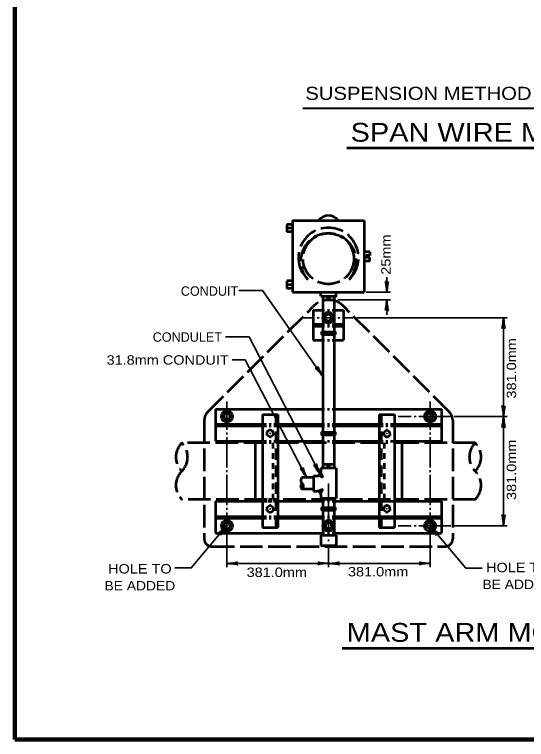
# Model space of a CAD drawing. Extents: x -35 to 821, y -10 to 534.
# Drawn here: x 22.7 to 185.9, y 1.2 to 232.3 of the extents above; entities that cross this region are included whole.
import ezdxf
from ezdxf.enums import TextEntityAlignment as Align

# ---------------------------------------------------------------- set-up
doc = ezdxf.new("R2010")
doc.units = 0
doc.header["$LTSCALE"] = 1.2
for name, pattern in [('LONG_DASHED', [7.5, 6, -1.5]), ('MEDIUM_DASHED', [4.5, 3, -1.5]), ('SHORT_DASHED', [2.7, 1.5, -1.2])]:
    doc.linetypes.add(name, pattern=pattern)
doc.layers.add('1', color=7, linetype='Continuous', lineweight=35)

msp = doc.modelspace()

# ---------------------------------------------------------------- hatches: boundary and pattern name
at = {"layer": '1'}
for points in [[(90.519, 104.186, 1), (90.219, 104.186, 1)], [(155.33, 104.153, 1), (155.03, 104.153, 1)], [(104.352, 98.795, 1), (104.052, 98.795, 1)], [(141.55, 98.74, 1), (141.25, 98.74, 1)], [(104.348, 74.708, 1), (104.047, 74.708, 1)], [(141.55, 74.781, 1), (141.25, 74.781, 1)], [(90.548, 69.401, 1), (90.248, 69.401, 1)], [(122.966, 69.335, 1), (122.666, 69.335, 1)], [(155.345, 69.345, 1), (155.045, 69.345, 1)]]:
    msp.add_hatch(color=256, dxfattribs=at).paths.add_polyline_path(points)

# ---------------------------------------------------------------- linework, layer by layer
at = {"layer": '1', "lineweight": 40}
msp.add_line((114.635, 202.436), (284.928, 202.436), dxfattribs=at)
at = {"layer": '1', "lineweight": 53}
for p, q in [((128.665, 189.734), (273.471, 189.734)), ((111.353, 166.568), (111.353, 143.768)), ((111.353, 166.568), (134.194, 166.568)), ((134.194, 166.568), (134.194, 143.768)), ((111.353, 165.368), (109.553, 165.368)), ((109.553, 165.368), (109.553, 162.968)), ((111.353, 164.168), (109.553, 164.168)), ((111.353, 162.968), (109.553, 162.968)), ((135.994, 156.668), (134.194, 156.668)), ((135.994, 155.468), (134.794, 155.468)), ((135.994, 156.668), (135.994, 155.468)), ((135.994, 153.668), (135.994, 154.868)), ((135.994, 153.668), (134.194, 153.668)), ((111.353, 147.368), (109.553, 147.368)), ((109.553, 147.368), (109.553, 144.968)), ((111.353, 146.168), (109.553, 146.168)), ((111.353, 144.968), (109.553, 144.968)), ((111.353, 143.768), (134.194, 143.768)), ((120.353, 142.55), (120.353, 143.75)), ((120.994, 142.55), (120.994, 131.15)), ((120.994, 141.35), (124.594, 141.35)), ((122.194, 141.95), (123.394, 141.95)), ((124.594, 142.55), (124.594, 138.049)), ((122.453, 138.05), (123.094, 138.05)), ((124.594, 138.035), (124.594, 131.15)), ((127.594, 138.05), (127.594, 128.45)), ((121.862, 135.102), (121.862, 136.262)), ((123.687, 135.682), (123.687, 136.262)), ((123.687, 135.682), (123.687, 135.102)), ((117.953, 132.95), (120.994, 132.95)), ((120.994, 132.95), (121.553, 132.95)), ((122.453, 133.55), (123.094, 133.55)), ((122.453, 132.95), (123.094, 132.95)), ((123.994, 133.55), (124.594, 133.55)), ((123.994, 132.95), (124.594, 132.95)), ((124.594, 133.55), (127.594, 133.55)), ((124.594, 132.95), (127.594, 132.95)), ((120.994, 131.15), (124.594, 131.15)), ((120.994, 130.25), (124.594, 130.25)), ((120.994, 130.25), (120.994, 101.15)), ((124.594, 130.25), (124.594, 99.2)), ((117.953, 128.45), (121.553, 128.45)), ((122.453, 128.45), (123.094, 128.45)), ((123.994, 128.45), (127.594, 128.45)), ((86.794, 106.55), (121.553, 106.55)), ((122.453, 106.55), (123.094, 106.55)), ((123.994, 106.55), (158.794, 106.55)), ((158.794, 106.55), (158.794, 96.35)), ((89.482, 103.616), (89.482, 104.777)), ((91.307, 104.197), (91.307, 104.777)), ((91.307, 104.197), (91.307, 103.616)), ((101.794, 104.75), (101.794, 68.75)), ((101.794, 104.75), (106.594, 104.75)), ((106.594, 104.75), (106.594, 68.75)), ((138.994, 104.75), (138.994, 68.75)), ((138.994, 104.75), (143.794, 104.75)), ((143.794, 104.75), (143.794, 68.75)), ((154.282, 103.616), (154.282, 104.777)), ((156.107, 104.197), (156.107, 104.777)), ((156.107, 104.197), (156.107, 103.616)), ((86.794, 101.75), (102.994, 101.75)), ((103.894, 101.75), (104.494, 101.75)), ((105.394, 101.75), (121.553, 101.75)), ((122.453, 101.75), (123.094, 101.75)), ((123.994, 101.75), (140.194, 101.75)), ((141.094, 101.75), (141.694, 101.75)), ((142.594, 101.75), (158.794, 101.75)), ((86.794, 101.15), (102.994, 101.15)), ((103.293, 98.196), (103.293, 99.356)), ((103.894, 101.15), (104.494, 101.15)), ((105.118, 98.776), (105.118, 99.356)), ((105.394, 101.15), (121.553, 101.15)), ((120.994, 101.15), (120.994, 99.2)), ((122.453, 101.15), (123.094, 101.15)), ((123.994, 101.15), (140.194, 101.15)), ((141.094, 101.15), (141.694, 101.15)), ((142.594, 101.15), (158.794, 101.15)), ((105.118, 98.776), (105.118, 98.196)), ((120.994, 99.2), (124.594, 99.2)), ((120.994, 98.3), (124.594, 98.3)), ((120.994, 98.3), (120.994, 96.35)), ((124.594, 98.3), (124.594, 87.65)), ((140.491, 98.14), (140.491, 99.301)), ((142.316, 98.72), (142.316, 99.301)), ((142.316, 98.72), (142.316, 98.14)), ((86.794, 96.35), (102.994, 96.35)), ((99.394, 95.75), (99.394, 77.75)), ((103.894, 96.35), (104.494, 96.35)), ((105.394, 96.35), (121.553, 96.35)), ((120.994, 96.35), (120.994, 87.65)), ((122.453, 96.35), (123.094, 96.35)), ((123.994, 96.35), (140.194, 96.35)), ((141.094, 96.35), (141.694, 96.35)), ((142.594, 96.35), (158.794, 96.35)), ((146.194, 95.75), (146.194, 77.75)), ((124.594, 88.85), (120.994, 88.85)), ((123.394, 88.249), (122.194, 88.249)), ((125.194, 87.65), (120.396, 87.65)), ((120.396, 87.65), (120.396, 86.45)), ((125.194, 87.65), (125.194, 78.05)), ((117.994, 84.677), (114.394, 84.677)), ((117.994, 85.276), (117.994, 80.422)), ((117.994, 85.276), (119.194, 85.276)), ((117.994, 81.022), (114.394, 81.022)), ((117.994, 80.422), (119.194, 80.422)), ((120.4, 79.249), (120.4, 78.05)), ((86.794, 77.15), (103.235, 77.15)), ((103.611, 77.15), (104.783, 77.15)), ((105.234, 77.15), (121.553, 77.15)), ((125.194, 78.05), (120.4, 78.05)), ((120.994, 78.05), (120.994, 77.15)), ((120.994, 77.15), (120.994, 75.2)), ((122.453, 77.15), (123.094, 77.15)), ((123.994, 77.15), (158.794, 77.15)), ((124.594, 78.05), (124.594, 77.15)), ((124.594, 77.15), (124.594, 75.2)), ((158.794, 77.15), (158.794, 66.95)), ((103.282, 74.14), (103.282, 75.3)), ((105.107, 74.72), (105.107, 75.3)), ((105.107, 74.72), (105.107, 74.14)), ((120.994, 75.2), (124.594, 75.2)), ((120.994, 74.3), (124.594, 74.3)), ((120.994, 74.3), (120.994, 72.35)), ((124.594, 74.3), (124.594, 72.35)), ((142.316, 74.761), (142.316, 75.342)), ((142.316, 74.761), (142.316, 74.181)), ((86.794, 72.35), (102.994, 72.35)), ((86.794, 71.75), (102.994, 71.75)), ((103.894, 72.35), (104.494, 72.35)), ((103.894, 71.75), (104.494, 71.75)), ((105.394, 72.35), (121.553, 72.35)), ((105.394, 71.75), (121.553, 71.75)), ((120.994, 72.35), (120.994, 66.35)), ((122.453, 72.35), (123.094, 72.35)), ((122.453, 71.75), (123.094, 71.75)), ((123.994, 72.35), (158.794, 72.35)), ((123.994, 71.75), (158.794, 71.75)), ((124.594, 72.35), (124.594, 66.35)), ((89.483, 68.792), (89.483, 69.953)), ((91.308, 69.373), (91.308, 69.953)), ((91.308, 69.373), (91.308, 68.792)), ((121.924, 68.755), (121.924, 69.916)), ((123.749, 69.335), (123.749, 69.916)), ((123.749, 69.335), (123.749, 68.755)), ((154.269, 68.764), (154.269, 69.925)), ((156.094, 69.344), (156.094, 69.925)), ((156.094, 69.344), (156.094, 68.764)), ((101.794, 68.75), (106.594, 68.75)), ((138.994, 68.75), (143.794, 68.75)), ((86.794, 66.95), (121.553, 66.95)), ((120.4, 66.35), (125.254, 66.35)), ((120.4, 66.35), (120.4, 63.05)), ((122.453, 66.95), (123.094, 66.95)), ((123.994, 66.95), (158.794, 66.95)), ((125.254, 66.35), (125.254, 63.05)), ((120.4, 63.05), (125.254, 63.05)), ((127.119, 30.379), (264.717, 30.379))]:
    msp.add_line(p, q, dxfattribs=at)
at = {"layer": '1'}
for p, q in [((141.394, 143.768), (141.394, 148.568)), ((134.794, 143.768), (142.594, 143.768)), ((125.794, 141.35), (142.594, 141.35)), ((141.394, 141.35), (141.394, 136.55)), ((114.953, 135.65), (118.274, 135.65)), ((119.174, 135.65), (119.774, 135.65)), ((120.674, 135.65), (124.894, 135.65)), ((125.794, 135.65), (126.394, 135.65)), ((127.294, 135.65), (130.594, 135.65)), ((131.794, 135.65), (179.794, 135.65)), ((90.394, 108.95), (90.394, 99.95)), ((155.194, 108.95), (155.194, 99.95)), ((145.03, 104.15), (149.194, 104.15)), ((150.094, 104.15), (150.694, 104.15)), ((151.594, 104.15), (161.644, 104.15)), ((162.844, 104.15), (179.794, 104.15)), ((90.394, 99.05), (90.394, 98.45)), ((90.394, 97.55), (90.394, 87.95)), ((155.194, 99.05), (155.194, 98.45)), ((155.194, 97.55), (155.194, 87.95)), ((90.394, 87.05), (90.394, 86.45)), ((90.394, 85.55), (90.394, 75.95)), ((155.194, 87.05), (155.194, 86.45)), ((155.194, 85.55), (155.194, 75.95)), ((122.827, 75.2), (122.827, 82.85)), ((90.394, 75.05), (90.394, 74.45)), ((122.827, 74.6), (122.827, 74.9)), ((122.827, 66.35), (122.827, 74.3)), ((155.194, 75.05), (155.194, 74.45)), ((90.394, 73.55), (90.394, 56.15)), ((155.194, 73.55), (155.194, 56.15)), ((145.03, 69.35), (149.194, 69.35)), ((150.094, 69.35), (150.694, 69.35)), ((151.594, 69.35), (161.794, 69.35)), ((162.994, 69.35), (179.794, 69.35)), ((122.827, 64.4), (122.827, 65)), ((122.827, 62.6), (122.827, 56.15))]:
    msp.add_line(p, q, dxfattribs=at)
at = {"layer": '1', "linetype": 'LONG_DASHED', "lineweight": 53}
for p, q in [((84.249, 105.532), (117.85, 139.133)), ((161.34, 105.532), (127.739, 139.133)), ((83.194, 102.986), (83.194, 65.156)), ((162.394, 102.986), (162.394, 65.156)), ((102.994, 95.75), (75.994, 95.75)), ((104.494, 95.75), (103.894, 95.75)), ((140.194, 95.75), (105.394, 95.75)), ((141.694, 95.75), (141.094, 95.75)), ((169.594, 95.75), (142.594, 95.75)), ((103.213, 77.75), (75.994, 77.75)), ((104.686, 77.75), (103.665, 77.75)), ((169.594, 77.75), (105.137, 77.75)), ((85.594, 62.756), (159.994, 62.756))]:
    msp.add_line(p, q, dxfattribs=at)
at = {"layer": '1', "linetype": 'MEDIUM_DASHED', "lineweight": 53}
for p, q in [((105.994, 104.75), (105.994, 68.75)), ((139.594, 104.75), (139.594, 68.75))]:
    msp.add_line(p, q, dxfattribs=at)
at = {"layer": '1', "linetype": 'SHORT_DASHED', "lineweight": 53}
for p, q in [((105.094, 95.75), (105.094, 77.75)), ((140.494, 95.75), (140.494, 77.75))]:
    msp.add_line(p, q, dxfattribs=at)
at = {"layer": '1', "lineweight": 158}
msp.add_line((814.384, 1.25), (22.784, 1.25), dxfattribs=at)
msp.add_lwpolyline([(814.384, 527.35), (22.684, 527.25), (22.784, 1.25)], dxfattribs=at)
at = {"layer": '1', "lineweight": 53}
for points in [[(135.994, 154.868), (134.794, 154.868), (134.794, 155.468)], [(120.353, 142.55), (125.194, 142.55), (125.194, 143.75)], [(117.953, 138.05), (120.994, 138.05), (121.553, 138.05)], [(117.953, 138.05), (117.953, 132.95), (117.953, 128.45)], [(121.862, 136.262), (122.775, 136.828), (123.687, 136.262)], [(123.994, 138.05), (124.594, 138.05), (127.594, 138.05)], [(123.687, 135.102), (122.775, 134.538), (121.862, 135.102)], [(117.953, 133.55), (120.994, 133.55), (121.553, 133.55)], [(86.794, 106.55), (86.794, 101.75), (86.794, 96.35)], [(89.482, 104.777), (90.394, 105.342), (91.307, 104.777)], [(154.282, 104.777), (155.194, 105.342), (156.107, 104.777)], [(91.307, 103.616), (90.394, 103.053), (89.482, 103.616)], [(156.107, 103.616), (155.194, 103.053), (154.282, 103.616)], [(103.293, 99.356), (104.205, 99.922), (105.118, 99.356)], [(140.491, 99.301), (141.404, 99.866), (142.316, 99.301)], [(105.118, 98.196), (104.205, 97.632), (103.293, 98.196)], [(142.316, 98.14), (141.404, 97.577), (140.491, 98.14)], [(120.302, 86.086), (120.884, 84.83), (119.574, 85.367)], [(120.306, 79.612), (120.888, 80.868), (119.578, 80.331)], [(86.794, 77.15), (86.794, 72.35), (86.794, 71.75), (86.794, 66.95)], [(103.282, 75.3), (104.195, 75.866), (105.107, 75.3)], [(105.107, 74.14), (104.195, 73.577), (103.282, 74.14)], [(140.491, 74.181), (140.491, 75.342), (141.404, 75.907), (142.316, 75.342)], [(142.316, 74.181), (141.404, 73.618), (140.491, 74.181)], [(89.483, 69.953), (90.395, 70.518), (91.308, 69.953)], [(121.924, 69.916), (122.836, 70.481), (123.749, 69.916)], [(154.269, 69.925), (155.181, 70.49), (156.094, 69.925)], [(91.308, 68.792), (90.395, 68.229), (89.483, 68.792)], [(123.749, 68.755), (122.836, 68.192), (121.924, 68.755)], [(156.094, 68.764), (155.181, 68.201), (154.269, 68.764)]]:
    msp.add_lwpolyline(points, dxfattribs=at)
at = {"layer": '1'}
for points in [[(120.994, 116.961), (101.724, 144.27), (94.238, 144.27)], [(178.594, 135.65), (178.594, 104.15), (178.594, 69.35)], [(120.092, 85.742), (97.498, 129.5), (89.923, 129.5)], [(115.818, 84.677), (96.222, 122.178), (92.093, 122.178)], [(90.273, 69.302), (79.027, 55.912), (73.769, 55.912)], [(155.306, 69.203), (166.552, 55.814), (171.81, 55.814)], [(90.394, 57.35), (122.827, 57.35), (155.194, 57.35)]]:
    msp.add_lwpolyline(points, dxfattribs=at)
at = {"layer": '1', "linetype": 'LONG_DASHED', "lineweight": 53}
msp.add_circle((122.761, 154.441), 8.1, dxfattribs=at)
at = {"layer": '1', "lineweight": 53}
for centre in [(122.789, 135.651), (90.409, 104.166), (155.209, 104.166), (90.41, 69.342), (122.801, 69.362), (155.196, 69.314)]:
    msp.add_circle(centre, 1.779, dxfattribs=at)
at = {"layer": '1', "lineweight": 13}
for centre in [(90.369, 104.186), (155.18, 104.153), (104.202, 98.795), (141.4, 98.74), (104.198, 74.708), (141.4, 74.781), (90.398, 69.401), (122.816, 69.335), (155.195, 69.345)]:
    msp.add_circle(centre, 0.15, dxfattribs=at)
at = {"layer": '1', "lineweight": 53}
for centre, radius, start, end in [((122.774, 164.399), 3.791, 37.18292, 142.81708), ((120.957, 130.7), 0.452, 85.2092, 274.79081), ((124.632, 130.7), 0.452, 265.20919, 94.7908), ((120.957, 98.75), 0.452, 85.2092, 274.79081), ((124.632, 98.75), 0.452, 265.20919, 94.7908), ((119.08, 86.595), 1.324, 291.91656, 353.67636), ((119.08, 86.595), 1.324, 291.91738, 337.37313), ((115.084, 83.763), 1.145, 127.04437, 232.95563), ((119.08, 86.595), 1.324, 274.9623, 291.91656), ((115.084, 81.936), 1.145, 127.04437, 232.95563), ((113.691, 81.936), 1.145, 307.04437, 52.95563), ((119.084, 79.103), 1.324, 68.08344, 85.22882), ((119.084, 79.103), 1.324, 6.34541, 68.08344), ((119.084, 79.103), 1.324, 22.62687, 68.08262), ((120.957, 74.75), 0.452, 85.2092, 274.79081), ((124.632, 74.75), 0.452, 265.20919, 94.7908)]:
    msp.add_arc(centre, radius, start, end, dxfattribs=at)
at = {"layer": '1', "linetype": 'LONG_DASHED', "lineweight": 53}
for centre, radius, start, end in [((122.774, 154.757), 9.57, 313.60282, 226.39718), ((122.774, 153.704), 8.837, 318.31863, 221.68137), ((122.794, 134.729), 6.621, 41.68937, 138.31063), ((86.794, 102.986), 3.6, 135, 180), ((158.794, 102.986), 3.6, 0, 45), ((80.443, 91.25), 6.327, 134.66789, 225.33211), ((71.57, 91.25), 6.327, 314.66789, 45.33211), ((174.019, 91.25), 6.327, 134.66789, 225.33211), ((165.146, 91.25), 6.327, 314.66789, 45.33211), ((80.443, 82.25), 6.327, 134.66789, 225.33211), ((165.146, 82.25), 6.327, 314.66789, 45.33211), ((85.594, 65.156), 2.4, 180, 270), ((159.994, 65.156), 2.4, 270, 0)]:
    msp.add_arc(centre, radius, start, end, dxfattribs=at)
at = {"layer": '1', "lineweight": 40}
for centre, major_axis, ratio, start_param, end_param in [((141.063, 145.077), (0.187, -2.143), 0.122415, 0.8963533, 3.1415927), ((141.063, 145.077), (0.187, -2.143), 0.122415, 0.8963533, 3.1415927), ((141.648, 145.112), (-0.211, -2.108), 0.07063, 3.1407148, 5.41811), ((141.648, 145.112), (-0.211, -2.108), 0.07063, 3.1407148, 5.41811), ((141.14, 140.005), (0.211, 2.108), 0.07063, 3.1407148, 5.41811), ((141.726, 140.04), (-0.187, 2.143), 0.122415, 0.8963533, 3.1415927), ((178.34, 134.305), (0.211, 2.108), 0.07063, 3.1407148, 5.41811), ((178.34, 134.305), (0.211, 2.108), 0.07063, 3.1407148, 5.41811), ((178.926, 134.34), (-0.187, 2.143), 0.122415, 0.8963533, 3.1415927), ((178.926, 134.34), (-0.187, 2.143), 0.122415, 0.8963533, 3.1415927), ((119.969, 117.84), (1.389, -1.643), 0.122415, 0.8963533, 3.1415927), ((119.969, 117.84), (1.389, -1.643), 0.122415, 0.8963533, 3.1415927), ((120.427, 118.206), (-1.043, 1.844), 0.07063, 6.2823074, 8.5597026), ((120.427, 118.206), (-1.043, 1.844), 0.07063, 6.2823074, 8.5597026), ((178.263, 105.459), (0.187, -2.143), 0.122415, 0.8963533, 3.1415927), ((178.263, 105.459), (0.187, -2.143), 0.122415, 0.8963533, 3.1415927), ((178.848, 105.494), (-0.211, -2.108), 0.07063, 3.1407148, 5.41811), ((178.848, 105.494), (-0.211, -2.108), 0.07063, 3.1407148, 5.41811), ((178.34, 102.805), (0.211, 2.108), 0.07063, 3.1407148, 5.41811), ((178.34, 102.805), (0.211, 2.108), 0.07063, 3.1407148, 5.41811), ((178.926, 102.84), (-0.187, 2.143), 0.122415, 0.8963533, 3.1415927), ((178.926, 102.84), (-0.187, 2.143), 0.122415, 0.8963533, 3.1415927), ((115.42, 85.986), (0.789, -1.966), 0.07063, 3.1407148, 5.41811), ((119.197, 86.753), (1.15, -1.818), 0.122415, 0.8963533, 3.1415927), ((119.197, 86.753), (1.15, -1.818), 0.122415, 0.8963533, 3.1415927), ((119.701, 87.053), (0.78, -1.97), 0.07063, 3.1407148, 5.41811), ((119.701, 87.053), (0.78, -1.97), 0.07063, 3.1407148, 5.41811), ((114.918, 85.683), (1.159, -1.812), 0.122415, 0.8963533, 3.1415927), ((178.263, 70.659), (0.187, -2.143), 0.122415, 0.8963533, 3.1415927), ((178.848, 70.694), (-0.211, -2.108), 0.07063, 3.1407148, 5.41811), ((89.214, 68.435), (-1.517, -1.478), 0.07063, 6.2823074, 8.5597026), ((89.685, 68.086), (1.235, 1.761), 0.122415, 0.8963533, 3.1415927), ((155.894, 67.987), (-1.235, 1.761), 0.122415, 3.1415927, 5.386832), ((156.365, 68.337), (1.517, -1.478), 0.07063, 4.006668, 6.2840632), ((91.704, 57.681), (-2.143, -0.187), 0.122415, 0.8963533, 3.1415927), ((91.704, 57.681), (-2.143, -0.187), 0.122415, 0.8963533, 3.1415927), ((121.482, 57.604), (2.108, -0.211), 0.07063, 3.1407148, 5.41811), ((121.482, 57.604), (2.108, -0.211), 0.07063, 3.1407148, 5.41811), ((124.137, 57.681), (-2.143, -0.187), 0.122415, 0.8963533, 3.1415927), ((124.137, 57.681), (-2.143, -0.187), 0.122415, 0.8963533, 3.1415927), ((153.85, 57.604), (2.108, -0.211), 0.07063, 3.1407148, 5.41811), ((91.739, 57.096), (-2.108, 0.211), 0.07063, 3.1407148, 5.41811), ((91.739, 57.096), (-2.108, 0.211), 0.07063, 3.1407148, 5.41811), ((121.518, 57.018), (2.143, 0.187), 0.122415, 0.8963533, 3.1415927), ((121.518, 57.018), (2.143, 0.187), 0.122415, 0.8963533, 3.1415927), ((124.172, 57.096), (-2.108, 0.211), 0.07063, 3.1407148, 5.41811), ((124.172, 57.096), (-2.108, 0.211), 0.07063, 3.1407148, 5.41811), ((153.885, 57.018), (2.143, 0.187), 0.122415, 0.8963533, 3.1415927)]:
    msp.add_ellipse(centre, major_axis=major_axis, ratio=ratio, start_param=start_param, end_param=end_param, dxfattribs=at)

# ---------------------------------------------------------------- texts
at = {"layer": '1', "width": 1.15}
for s, height, p in [('SUSPENSION METHOD "B" - DOUBLE HANGER UNITS', 4.2, (115.397, 205.029)), ('SPAN WIRE MOUNTING DETAILS', 6, (129.83, 191.731)), ('31.8mm CONDUIT', 3, (52.033, 120.687)), ('381.0mm', 3, (96.688, 53.036)), ('381.0mm', 3, (129.003, 53.214)), ('MAST ARM MOUNTING DETAIL', 6, (128.604, 32.375))]:
    msp.add_text(s, height=height, dxfattribs=at).set_placement(p)
for s, p in [('25mm', (142.585, 149.34)), ('381.0mm', (182.61, 109.889)), ('381.0mm', (182.61, 77.566))]:
    msp.add_text(s, height=3, rotation=90, dxfattribs=at).set_placement(p)
at = {"layer": '1'}
for s, p in [('CONDUIT', (75.719, 142.632)), ('CONDULET', (66.758, 127.983))]:
    msp.add_text(s, height=3, dxfattribs=at).set_placement(p)
for s, width, p in [('HOLE TO', 1.15, (62.656, 54.138)), ('HOLE TO', 1.15, (183.143, 54.556)), ('BE ADDED', 1.1, (62.656, 48.738)), ('BE ADDED', 1.1, (183.143, 49.157))]:
    msp.add_text(s, height=3, dxfattribs=dict(at, width=width)).set_placement(p, align=Align.CENTER)

doc.saveas('drawing.dxf')
